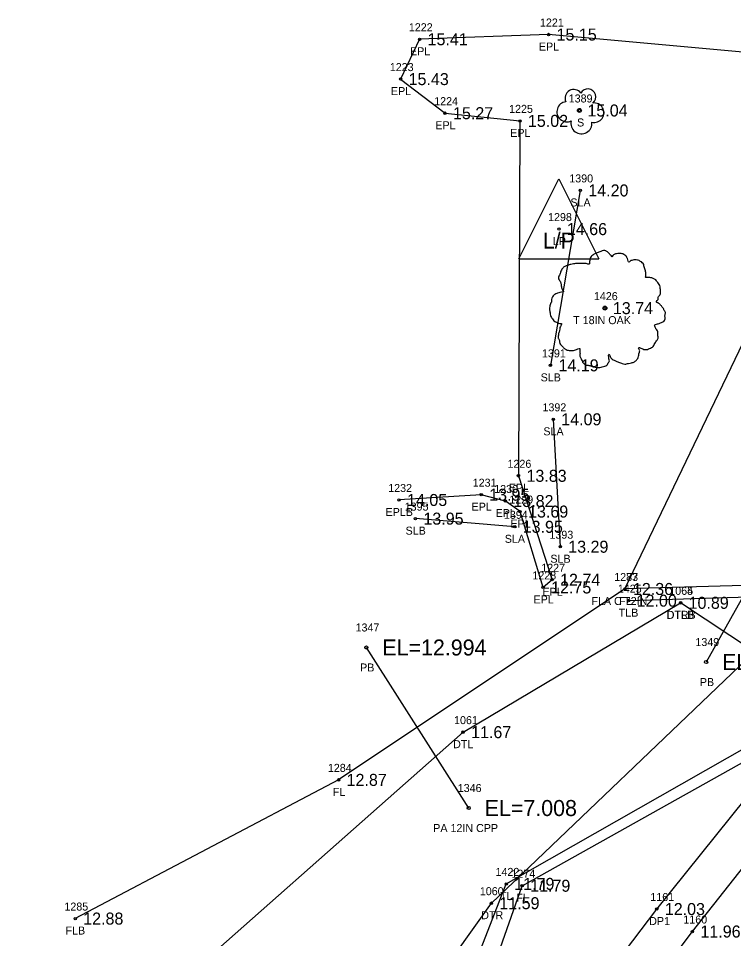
# Model space of a CAD drawing. Extents: x 2072307 to 2072993, y 127574 to 129736.
# Drawn here: x 2072682 to 2072771.4, y 128472.9 to 128587.8 of the extents above; entities that cross this region are included whole.
import ezdxf

# ---------------------------------------------------------------- set-up
doc = ezdxf.new("R2010")
doc.units = 0
for name, color, linetype in [('RD_EX_DR_Pipe', 7, 'Continuous'), ('RD_EX_DR_Pipe_txCode', 7, 'Continuous'), ('RD_EX_Driveway', 7, 'Continuous'), ('RD_EX_Driveway_txCode', 7, 'Continuous'), ('RD_EX_Fence_Other', 7, 'Continuous'), ('RD_EX_Fence_Other_txCode', 7, 'Continuous'), ('RD_EX_H2O', 7, 'Continuous'), ('RD_EX_H2O_txCode', 7, 'Continuous'), ('RD_EX_Road', 7, 'Continuous'), ('RD_EX_Road_txCode', 7, 'Continuous'), ('RD_EX_TX_Driveway_ELEV', 7, 'Continuous'), ('RD_EX_TX_Fence_Other_ELEV', 7, 'Continuous'), ('RD_EX_TX_H2O_ELEV', 7, 'Continuous'), ('RD_EX_TX_Road_ELEV', 7, 'Continuous'), ('RD_EX_TX_UT_ELEV', 7, 'Continuous'), ('RD_EX_TX_VEG_ELEV', 7, 'Continuous'), ('RD_EX_UT', 7, 'Continuous'), ('RD_EX_UT_txCode', 7, 'Continuous'), ('RD_EX_VEG', 7, 'Continuous'), ('RD_EX_VEG_txCode', 7, 'Continuous'), ('RD_SMD_Locator', 7, 'Continuous'), ('RD_TX_Pipe_ElevEX', 7, 'Continuous')]:
    doc.layers.add(name, color=color, linetype=linetype)

msp = doc.modelspace()

# ---------------------------------------------------------------- linework, layer by layer
at = {"layer": 'RD_EX_DR_Pipe'}
for p, q in [((2072791.89, 128550.08), (2072767.92, 128507.42)), ((2072738.25, 128489.18), (2072725.46, 128509.24))]:
    msp.add_line(p, q, dxfattribs=at)
at = {"layer": 'RD_EX_Driveway'}
for points in [[(2072694.21, 128239.74), (2072695.7, 128289.15), (2072695.56, 128330.43), (2072696.37, 128337.85), (2072700.81, 128345.17), (2072711.22, 128347.96), (2072719.56, 128349.59), (2072725.15, 128351.26), (2072733.07, 128358.33), (2072734.19, 128365.42), (2072741.79, 128414.16), (2072748.82, 128445.27), (2072754.15, 128456.57), (2072759.92, 128465.41), (2072766.21, 128473.75), (2072780.47, 128491.8), (2072796.27, 128516), (2072809.9, 128540.1), (2072821.01, 128555.78)], [(2072689.37, 128239.9), (2072690.93, 128289.43), (2072690.32, 128330.24), (2072690.73, 128338.81), (2072697.63, 128350.77), (2072709.38, 128353.48), (2072719, 128355.15), (2072723.52, 128356.83), (2072727.18, 128360.82), (2072729.07, 128366.04), (2072736.87, 128415.65), (2072743.44, 128446.63), (2072749.73, 128459.37), (2072755.76, 128468.63), (2072761.76, 128476.56), (2072776.61, 128495.01), (2072792.09, 128518.96), (2072805.19, 128542.59), (2072810.66, 128554.44), (2072797.46, 128551.01)]]:
    msp.add_lwpolyline(points, dxfattribs=at)
at = {"layer": 'RD_EX_Fence_Other'}
for points in [[(2072717.23, 128356.49), (2072726.05, 128417.31), (2072734.38, 128449.46), (2072744.93, 128479.47), (2072775.22, 128496.41), (2072780.14, 128517.18), (2072757.78, 128516.55), (2072777.16, 128556.96), (2072786.53, 128575.88)], [(2072757.78, 128516.55), (2072721.99, 128492.7), (2072689.07, 128475.37)]]:
    msp.add_lwpolyline(points, dxfattribs=at)
at = {"layer": 'RD_EX_H2O'}
for points in [[(2072699.9, 128366.65), (2072695.37, 128461.33), (2072737.55, 128498.66), (2072764.73, 128514.82)], [(2072699.9, 128366.65), (2072717.3, 128368.56), (2072719.94, 128447.6), (2072741.08, 128477.29), (2072773.98, 128508.7), (2072764.73, 128514.82)]]:
    msp.add_lwpolyline(points, dxfattribs=at)
at = {"layer": 'RD_EX_Road'}
msp.add_lwpolyline([(2072775.68, 128466.69), (2072812.91, 128539.86), (2072821.01, 128555.78), (2072820.61, 128560.93), (2072818.55, 128566.13), (2072816.34, 128569.6), (2072812.37, 128574.19), (2072803.55, 128578.22), (2072783.97, 128582.57), (2072748.23, 128585.83), (2072732.11, 128585.24), (2072729.74, 128580.26), (2072735.29, 128576), (2072744.65, 128575.04), (2072744.47, 128530.69), (2072748.67, 128517.7), (2072747.55, 128516.74), (2072744.67, 128526.22), (2072742.83, 128527.54), (2072739.81, 128528.33), (2072729.54, 128527.67)], dxfattribs=at)
at = {"layer": 'RD_EX_UT'}
for p, q in [((2072744.52, 128557.8), (2072749.52, 128567.8)), ((2072749.52, 128567.8), (2072754.52, 128557.8)), ((2072744.52, 128557.8), (2072754.52, 128557.8))]:
    msp.add_line(p, q, dxfattribs=at)
at = {"layer": 'RD_EX_VEG'}
for p, q in [((2072752.2, 128566.35), (2072748.47, 128544.49)), ((2072748.82, 128537.75), (2072749.69, 128521.83)), ((2072744, 128524.32), (2072731.59, 128525.34))]:
    msp.add_line(p, q, dxfattribs=at)
msp.add_lwpolyline([(2072681.97, 128364.24), (2072716.35, 128365.68), (2072731.52, 128450.35), (2072742.94, 128479.7), (2072773.31, 128497.01), (2072778.81, 128515.7), (2072758.24, 128515.09)], dxfattribs=at)
for centre, radius in [((2072752.09, 128576.34), 0.25), ((2072755.27, 128551.64), 0.25), ((2072755.26, 128551.62), 0.0001)]:
    msp.add_circle(centre, radius, dxfattribs=at)
for centre, radius, start, end in [((2072751.37, 128577.88), 1.08, 34.9763, 204.756), ((2072753.14, 128578.04), 0.995, 308.7626, 152.0467), ((2072750.53, 128576.18), 1.26, 96.4518, 294.734), ((2072753.93, 128576.06), 1.22, 256.5667, 98.1046), ((2072752.34, 128574.74), 1.32, 166.8827, 5.7589)]:
    msp.add_arc(centre, radius, start, end, dxfattribs=at)
for points in [[(2072755.4, 128558.81), (2072755.1, 128558.83), (2072754.78, 128558.73), (2072754.53, 128558.63), (2072754.3, 128558.56), (2072754.08, 128558.46), (2072753.78, 128558.28), (2072753.55, 128558.08), (2072753.43, 128557.83), (2072753.38, 128557.61), (2072753.33, 128557.33), (2072753.33, 128557.16), (2072753.2, 128557.13), (2072753.05, 128557.16), (2072752.81, 128557.23), (2072752.56, 128557.23), (2072752.31, 128557.23), (2072751.96, 128557.21), (2072751.61, 128557.21), (2072751.33, 128557.16), (2072751.01, 128557.11), (2072750.63, 128556.98), (2072750.28, 128556.86), (2072749.98, 128556.61), (2072749.73, 128556.13), (2072749.61, 128555.78), (2072749.46, 128555.53), (2072749.61, 128555.08), (2072749.78, 128554.73), (2072749.81, 128554.53), (2072749.88, 128554.11), (2072749.98, 128553.89), (2072750.11, 128553.69), (2072750.03, 128553.66), (2072749.66, 128553.61), (2072749.36, 128553.51), (2072748.93, 128553.29), (2072748.71, 128553.06), (2072748.61, 128552.74), (2072748.58, 128552.39), (2072748.48, 128552.19), (2072748.41, 128551.91), (2072748.38, 128551.84), (2072748.33, 128551.51), (2072748.43, 128551.06), (2072748.46, 128550.71), (2072748.58, 128550.49), (2072748.73, 128550.31), (2072748.91, 128550.06), (2072749.31, 128549.84), (2072749.63, 128549.74), (2072749.83, 128549.71), (2072749.66, 128549.21), (2072749.61, 128548.86), (2072749.48, 128548.46), (2072749.48, 128548.39), (2072749.43, 128547.91), (2072749.58, 128547.59), (2072749.66, 128547.21), (2072749.83, 128546.99), (2072750.11, 128546.69), (2072750.43, 128546.46), (2072750.93, 128546.34), (2072751.33, 128546.36), (2072751.91, 128546.54), (2072752.16, 128546.61), (2072752.13, 128546.44), (2072752.16, 128546.06), (2072752.16, 128545.64), (2072752.31, 128545.31), (2072752.41, 128545.04), (2072752.56, 128544.79), (2072752.88, 128544.56), (2072753.28, 128544.49), (2072753.7, 128544.34), (2072754.15, 128544.26), (2072754.65, 128544.24), (2072755.25, 128544.39), (2072755.53, 128544.51), (2072755.63, 128544.69), (2072755.83, 128545.06), (2072755.78, 128545.29), (2072755.8, 128545.89), (2072755.9, 128545.71), (2072756.08, 128545.36), (2072756.58, 128545.06), (2072756.98, 128544.89), (2072757.45, 128544.74), (2072757.75, 128544.66), (2072758.23, 128544.74), (2072758.6, 128544.81), (2072758.98, 128544.94), (2072759.28, 128545.21), (2072759.45, 128545.49), (2072759.5, 128545.76), (2072759.58, 128546.14), (2072759.63, 128546.31)], [(2072759.63, 128546.31), (2072759.55, 128546.49), (2072759.5, 128546.74), (2072759.58, 128546.71), (2072759.75, 128546.66), (2072760.03, 128546.54), (2072760.25, 128546.46), (2072760.58, 128546.49), (2072760.85, 128546.59), (2072761.3, 128546.86), (2072761.58, 128547.34), (2072761.85, 128547.74), (2072761.93, 128548.06), (2072761.88, 128548.29), (2072761.85, 128548.79), (2072761.65, 128549.04), (2072761.6, 128549.16), (2072761.5, 128549.56), (2072761.58, 128549.61), (2072761.85, 128549.66), (2072762.23, 128549.79), (2072762.5, 128549.91), (2072762.73, 128550.09), (2072762.8, 128550.31), (2072762.78, 128550.71), (2072762.83, 128551.11), (2072762.75, 128551.26), (2072762.65, 128551.41), (2072762.58, 128551.61), (2072762.43, 128551.76), (2072762.33, 128551.91), (2072762.23, 128552.01), (2072762.1, 128552.16), (2072761.93, 128552.29), (2072761.78, 128552.34), (2072761.73, 128552.49), (2072761.88, 128552.69), (2072761.93, 128552.79), (2072761.95, 128553.01), (2072762.18, 128553.36), (2072762.23, 128553.76), (2072762.18, 128554.18), (2072762.13, 128554.46), (2072761.98, 128554.73), (2072761.78, 128554.98), (2072761.65, 128555.16), (2072761.48, 128555.28), (2072761.15, 128555.41), (2072760.9, 128555.46), (2072760.55, 128555.46), (2072760.35, 128555.51), (2072760.38, 128555.56), (2072760.38, 128555.71), (2072760.38, 128555.98), (2072760.3, 128556.43), (2072760.15, 128556.93), (2072760.15, 128556.96), (2072760.05, 128557.21), (2072759.83, 128557.41), (2072759.65, 128557.51), (2072759.45, 128557.63), (2072759.2, 128557.66), (2072758.9, 128557.66), (2072758.63, 128557.61), (2072758.43, 128557.51), (2072758.25, 128557.38), (2072758.18, 128557.53), (2072758.08, 128557.83), (2072758.03, 128557.98), (2072757.88, 128558.16), (2072757.65, 128558.36), (2072757.2, 128558.48), (2072756.58, 128558.41), (2072756.28, 128558.21), (2072756.13, 128558.03), (2072756.08, 128558.16), (2072755.88, 128558.36), (2072755.78, 128558.53), (2072755.6, 128558.66), (2072755.45, 128558.76), (2072755.35, 128558.81)]]:
    msp.add_spline(points, degree=3, dxfattribs=at)
at = {"layer": 'RD_SMD_Locator'}
for centre, radius in [((2072748.23, 128585.83), 0.15), ((2072732.11, 128585.24), 0.15), ((2072729.74, 128580.26), 0.15), ((2072735.29, 128576), 0.15), ((2072752.09, 128576.34), 0.15), ((2072744.65, 128575.04), 0.15), ((2072752.2, 128566.35), 0.15), ((2072749.52, 128561.52), 0.15), ((2072755.27, 128551.64), 0.15), ((2072748.47, 128544.49), 0.15), ((2072748.82, 128537.75), 0.15), ((2072744.47, 128530.69), 0.15), ((2072739.81, 128528.33), 0.15), ((2072729.54, 128527.67), 0.15), ((2072742.83, 128527.54), 0.15), ((2072744.67, 128526.22), 0.15), ((2072731.59, 128525.34), 0.15), ((2072744, 128524.32), 0.15), ((2072749.69, 128521.83), 0.15), ((2072747.55, 128516.74), 0.15), ((2072748.67, 128517.7), 0.15), ((2072757.78, 128516.55), 0.15), ((2072757.78, 128516.55), 0.15), ((2072758.24, 128515.09), 0.15), ((2072764.73, 128514.82), 0.15), ((2072764.73, 128514.82), 0.15), ((2072725.46, 128509.24), 0.2), ((2072767.92, 128507.42), 0.2), ((2072737.55, 128498.66), 0.15), ((2072721.99, 128492.7), 0.15), ((2072738.25, 128489.18), 0.2), ((2072742.94, 128479.7), 0.15), ((2072744.93, 128479.47), 0.15), ((2072741.08, 128477.29), 0.15), ((2072761.76, 128476.56), 0.15), ((2072689.07, 128475.37), 0.15), ((2072766.21, 128473.75), 0.15)]:
    msp.add_circle(centre, radius, dxfattribs=at)

# ---------------------------------------------------------------- texts
at = {"layer": 'RD_EX_DR_Pipe_txCode'}
for s, p in [('1347', (2072724.11, 128511.24)), ('1349', (2072766.58, 128509.42)), ('PB', (2072724.68, 128506.24)), ('PB', (2072767.14, 128504.42)), ('1346', (2072736.88, 128491.18)), ('PA 12IN CPP', (2072733.82, 128486.18))]:
    msp.add_text(s, height=1, dxfattribs=at).set_placement(p)
at = {"layer": 'RD_EX_Driveway_txCode'}
for s, p in [('1161', (2072760.95, 128477.56)), ('DP1', (2072760.81, 128474.56)), ('1160', (2072765.08, 128474.75))]:
    msp.add_text(s, height=1, dxfattribs=at).set_placement(p)
at = {"layer": 'RD_EX_Fence_Other_txCode'}
for s, p in [('1277', (2072756.44, 128517.55)), ('1283', (2072756.44, 128517.55)), ('FLA C 72IN', (2072753.59, 128514.55)), ('FL', (2072757.05, 128514.55)), ('1284', (2072720.65, 128493.7)), ('FL', (2072721.26, 128490.7)), ('1274', (2072743.59, 128480.47)), ('FL', (2072744.2, 128477.47)), ('1285', (2072687.72, 128476.37)), ('FLB', (2072687.86, 128473.37))]:
    msp.add_text(s, height=1, dxfattribs=at).set_placement(p)
at = {"layer": 'RD_EX_H2O_txCode'}
for s, p in [('1064', (2072763.32, 128515.82)), ('1065', (2072763.32, 128515.82)), ('DTRB', (2072762.98, 128512.82)), ('DTLB', (2072763.01, 128512.82)), ('1061', (2072736.42, 128499.66)), ('DTL', (2072736.3, 128496.66)), ('1060', (2072739.64, 128478.29)), ('DTR', (2072739.82, 128475.29))]:
    msp.add_text(s, height=1, dxfattribs=at).set_placement(p)
at = {"layer": 'RD_EX_Road_txCode'}
for s, p in [('1222', (2072730.77, 128586.24)), ('1221', (2072747.16, 128586.83)), ('EPL', (2072747.02, 128583.83)), ('EPL', (2072730.91, 128583.24)), ('1223', (2072728.39, 128581.26)), ('EPL', (2072728.53, 128578.26)), ('1224', (2072733.94, 128577)), ('1225', (2072743.3, 128576.04)), ('EPL', (2072734.08, 128574)), ('EPL', (2072743.44, 128573.04)), ('1226', (2072743.1, 128531.69)), ('1232', (2072728.19, 128528.67)), ('1231', (2072738.75, 128529.33)), ('1230', (2072741.44, 128528.54)), ('EPL', (2072743.26, 128528.69)), ('EPL', (2072738.61, 128526.33)), ('1229', (2072743.33, 128527.22)), ('EPLB', (2072727.86, 128525.67)), ('EPL', (2072741.62, 128525.54)), ('EPL', (2072743.47, 128524.22)), ('1227', (2072747.32, 128518.7)), ('1228', (2072746.21, 128517.74)), ('EPL', (2072746.35, 128514.74)), ('EPL', (2072747.47, 128515.7))]:
    msp.add_text(s, height=1, dxfattribs=at).set_placement(p)
at = {"layer": 'RD_EX_TX_Driveway_ELEV'}
for s, p in [('12.03', (2072762.76, 128475.81)), ('11.96', (2072767.21, 128473))]:
    msp.add_text(s, height=1.5, dxfattribs=at).set_placement(p)
at = {"layer": 'RD_EX_TX_Fence_Other_ELEV'}
for s, p in [('12.36', (2072758.78, 128515.8)), ('12.36', (2072758.78, 128515.8)), ('12.87', (2072722.99, 128491.95)), ('11.79', (2072745.93, 128478.72)), ('12.88', (2072690.07, 128474.62))]:
    msp.add_text(s, height=1.5, dxfattribs=at).set_placement(p)
at = {"layer": 'RD_EX_TX_H2O_ELEV'}
for s, p in [('10.89', (2072765.73, 128514.07)), ('10.89', (2072765.73, 128514.07)), ('11.67', (2072738.55, 128497.91)), ('11.59', (2072742.08, 128476.54))]:
    msp.add_text(s, height=1.5, dxfattribs=at).set_placement(p)
at = {"layer": 'RD_EX_TX_Road_ELEV'}
for s, p in [('15.41', (2072733.11, 128584.49)), ('15.15', (2072749.23, 128585.08)), ('15.43', (2072730.74, 128579.51)), ('15.27', (2072736.29, 128575.25)), ('15.02', (2072745.65, 128574.29)), ('13.83', (2072745.47, 128529.94)), ('14.05', (2072730.54, 128526.92)), ('13.95', (2072740.81, 128527.58)), ('13.82', (2072743.83, 128526.79)), ('13.69', (2072745.67, 128525.47)), ('12.74', (2072749.67, 128516.95)), ('12.75', (2072748.55, 128515.99))]:
    msp.add_text(s, height=1.5, dxfattribs=at).set_placement(p)
at = {"layer": 'RD_EX_TX_UT_ELEV'}
msp.add_text('14.66', height=1.5, dxfattribs=at).set_placement((2072750.52, 128560.77))
at = {"layer": 'RD_EX_TX_VEG_ELEV'}
for s, p in [('15.04', (2072753.09, 128575.59)), ('14.20', (2072753.2, 128565.6)), ('13.74', (2072756.27, 128550.89)), ('14.19', (2072749.47, 128543.74)), ('14.09', (2072749.82, 128537)), ('13.95', (2072732.59, 128524.59)), ('13.95', (2072745, 128523.57)), ('13.29', (2072750.69, 128521.08)), ('12.00', (2072759.24, 128514.34)), ('11.79', (2072743.94, 128478.95))]:
    msp.add_text(s, height=1.5, dxfattribs=at).set_placement(p)
at = {"layer": 'RD_EX_UT'}
msp.add_text('L/P', height=2, dxfattribs=at).set_placement((2072747.51, 128559.08))
at = {"layer": 'RD_EX_UT_txCode'}
for s, p in [('1298', (2072748.17, 128562.52)), ('LP', (2072748.76, 128559.52))]:
    msp.add_text(s, height=1, dxfattribs=at).set_placement(p)
at = {"layer": 'RD_EX_VEG_txCode'}
for s, p in [('1389', (2072750.75, 128577.34)), ('S', (2072751.79, 128574.34)), ('1390', (2072750.82, 128567.35)), ('SLA', (2072750.96, 128564.35)), ('1426', (2072753.9, 128552.64)), ('T 18IN OAK', (2072751.31, 128549.64)), ('1391', (2072747.41, 128545.49)), ('SLB', (2072747.24, 128542.49)), ('1392', (2072747.47, 128538.75)), ('SLA', (2072747.58, 128535.75)), ('1395', (2072730.25, 128526.34)), ('1394', (2072742.65, 128525.32)), ('SLB', (2072730.36, 128523.34)), ('1393', (2072748.34, 128522.83)), ('SLA', (2072742.76, 128522.32)), ('SLB', (2072748.46, 128519.83)), ('1425', (2072756.89, 128516.09)), ('TLB', (2072757, 128513.09)), ('1422', (2072741.6, 128480.7)), ('TL', (2072742.17, 128477.7))]:
    msp.add_text(s, height=1, dxfattribs=at).set_placement(p)
at = {"layer": 'RD_TX_Pipe_ElevEX'}
for s, p in [('EL=12.994', (2072727.46, 128508.24)), ('EL=6.487', (2072769.92, 128506.42)), ('EL=7.008', (2072740.25, 128488.18))]:
    msp.add_text(s, height=2, dxfattribs=at).set_placement(p)

doc.saveas('drawing.dxf')
